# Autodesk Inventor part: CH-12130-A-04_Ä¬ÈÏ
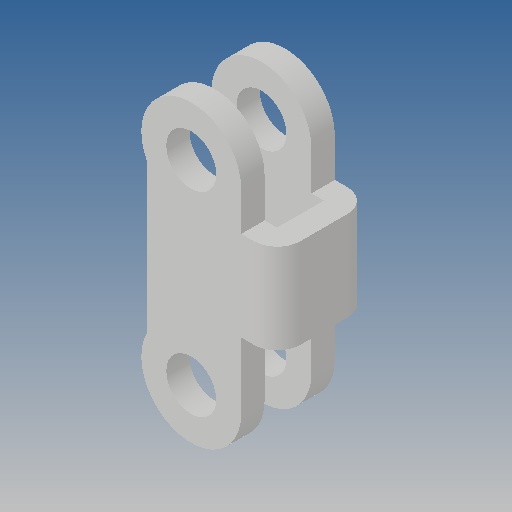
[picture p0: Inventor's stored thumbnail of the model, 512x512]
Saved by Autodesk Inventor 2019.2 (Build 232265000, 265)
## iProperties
Created: 2010-06
Part Number: CH-12130-A-04_Ä¬ÈÏ
Material: Ogólny
Document SubType Name: Modeling
Designer: CADENGINEERING4
Density: 1 g/cm^3
Appearance: Domyślna
Author: CADENGINEERING4
Revision Number: ÈÎºÎ
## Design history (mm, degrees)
feature "NONE"
node "Bryła1"
